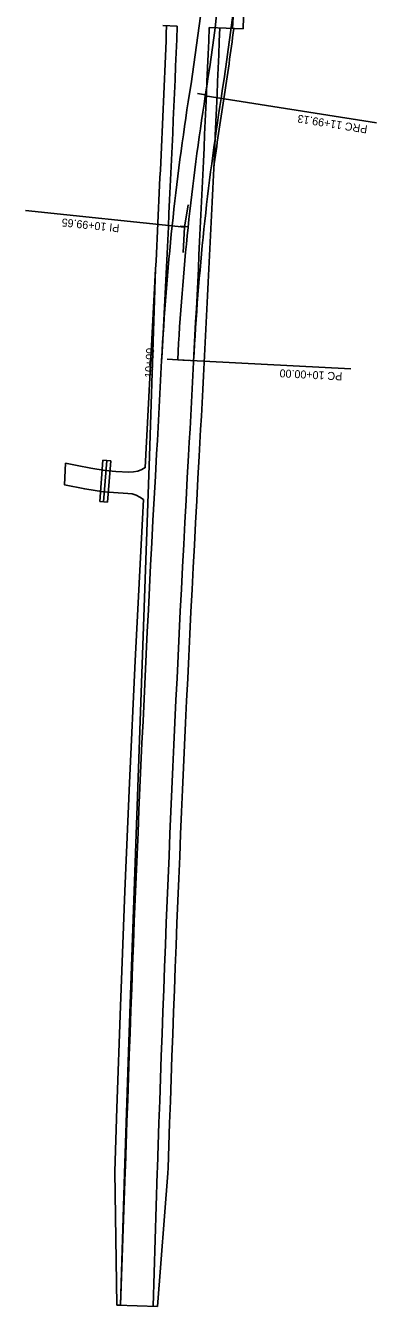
# Model space of a CAD drawing. Extents: x 1445610 to 1446352, y 2042797 to 2056486.
# Drawn here: x 1445971 to 1446234, y 2042797 to 2043758 of the extents above; entities that cross this region are included whole.
import ezdxf

# ---------------------------------------------------------------- set-up
doc = ezdxf.new("R2010")
doc.units = 0
for name, color, linetype in [('20', 7, 'Continuous'), ('Level 43', 7, 'Continuous'), ('R_Horz Alg', 7, 'Continuous'), ('R_Horz Alg Annot', 7, 'Continuous'), ('R_Horz Alg Stationing', 7, 'Continuous'), ('R_Proposed Road', 7, 'Continuous')]:
    doc.layers.add(name, color=color, linetype=linetype)

msp = doc.modelspace()

# ---------------------------------------------------------------- linework, layer by layer
at = {"layer": '20'}
msp.add_lwpolyline([(1446039.39, 2042798.44), (1446037.68, 2042898.55), (1446039.25, 2042946.21), (1446041.96, 2043022.64), (1446045.34, 2043108.8), (1446048.81, 2043189.97), (1446053.07, 2043281.49), (1446058.5, 2043388.13), (1446059.27, 2043402.53), (1446056.56, 2043404.44), (1446053.87, 2043405.76), (1446050.83, 2043406.71), (1446047.52, 2043407.17), (1446036.89, 2043407.75), (1446029.19, 2043408.39), (1446015.24, 2043410.54), (1446000.1, 2043413.57), (1446000.8, 2043429.75), (1446009.59, 2043427.99), (1446019.78, 2043425.96), (1446030.64, 2043424.33), (1446038.51, 2043423.68), (1446048.39, 2043423.14), (1446051.73, 2043423.24), (1446055.16, 2043423.94), (1446058.14, 2043425.09), (1446060.57, 2043426.48), (1446068.41, 2043575.65), (1446063.79, 2043435.13), (1446056.6, 2043229.42), (1446048.35, 2042995.93), (1446045.17, 2042897.14), (1446041.99, 2042798.36)], close=True, dxfattribs=at)
at = {"layer": 'Level 43'}
for p, q in [((1446026.42, 2043400.96), (1446028.9, 2043432.06)), ((1446028.9, 2043432.06), (1446034.88, 2043431.59)), ((1446029.41, 2043400.72), (1446031.89, 2043431.82)), ((1446032.4, 2043400.48), (1446034.88, 2043431.59)), ((1446026.42, 2043400.96), (1446032.4, 2043400.48))]:
    msp.add_line(p, q, dxfattribs=at)
at = {"layer": 'R_Horz Alg'}
for centre, start, end in [((1444219.17, 2044002.87), 351.0345, 358.09132), ((1447992.22, 2043407.6), 171.0345, 177.00833)]:
    msp.add_arc(centre, 1909.86, start, end, dxfattribs=at)
at = {"layer": 'R_Horz Alg Annot'}
for q in [(1446092.82, 2043623.62), (1446089.17, 2043587.8)]:
    msp.add_line((1446090.16, 2043606.8), q, dxfattribs=at)
for points in [[(1446105.69, 2043705.23), (1446234.11, 2043684.98)], [(1446090.16, 2043606.8), (1445970.82, 2043619.3)], [(1446084.96, 2043507.28), (1446214.79, 2043500.5)]]:
    msp.add_lwpolyline(points, dxfattribs=at)
at = {"layer": 'R_Horz Alg Stationing'}
for points in [[(1446099.9, 2043707.03), (1446105.83, 2043706.1)], [(1446086.83, 2043607.59), (1446092.79, 2043606.96)], [(1446076.97, 2043507.7), (1446092.95, 2043506.86)]]:
    msp.add_lwpolyline(points, dxfattribs=at)
at = {"layer": 'R_Proposed Road'}
for p, q in [((1446073.76, 2043757.95), (1446084.66, 2043757.5)), ((1446134.12, 2043755.46), (1446108.64, 2043756.51)), ((1446045.67, 2042898.29), (1446041.99, 2042798.36)), ((1446045.67, 2042898.29), (1446045.81, 2042902.42)), ((1446069.66, 2042897.52), (1446066.44, 2042797.57)), ((1446069.66, 2042897.52), (1446069.79, 2042901.66)), ((1446069.7, 2042797.47), (1446077.66, 2042897.27)), ((1446077.66, 2042897.27), (1446077.79, 2042901.4))]:
    msp.add_line(p, q, dxfattribs=at)
msp.add_lwpolyline([(1446069.7, 2042797.47), (1446039.39, 2042798.44)], dxfattribs=at)
for centre, radius, start, end in [((1423197.89, 2044703.4), 22947.81, 357.633333, 358.333333), ((1423197.89, 2044703.4), 22955.81, 357.633333, 358.333333), ((1444219.17, 2044002.87), 1897.86, 351.0345, 358.09132), ((1444219.17, 2044002.87), 1921.86, 351.0345, 358.09132), ((1423197.89, 2044703.4), 22898.31, 357.177015, 357.633333), ((1423197.89, 2044703.4), 22906.31, 356.830169, 357.633333), ((1423197.89, 2044703.4), 22930.31, 356.830169, 357.633333), ((1423197.89, 2044703.4), 22938.31, 356.830169, 357.633333), ((1444219.17, 2044002.87), 1923.86, 351.0345, 352.61997), ((1447992.22, 2043407.6), 1921.86, 171.0345, 177.00833), ((1447992.22, 2043407.6), 1897.86, 171.0345, 177.00833), ((1447992.22, 2043407.6), 1895.86, 171.0345, 172.62609), ((1468964.38, 2042168.83), 22930.31, 176.830169, 178.166667), ((1468964.38, 2042168.83), 22906.31, 176.830169, 178.166667), ((1468964.38, 2042168.83), 22898.31, 176.830169, 178.166667)]:
    msp.add_arc(centre, radius, start, end, dxfattribs=at)

# ---------------------------------------------------------------- texts
at = {"layer": 'R_Horz Alg Annot'}
for s, rotation, p in [('PRC 11+99.13', 171.0345, (1446227.71, 2043682.95)), ('PI 10+99.65', 174.02142, (1446041.49, 2043608.88)), ('PC 10+00.00', 177.00833, (1446208.64, 2043497.81))]:
    msp.add_text(s, height=6, rotation=rotation, dxfattribs=at).set_placement(p)
at = {"layer": 'R_Horz Alg Stationing'}
msp.add_text('10+00', height=6, rotation=87.00833, dxfattribs=at).set_placement((1446066.22, 2043493.59))

doc.saveas('drawing.dxf')
